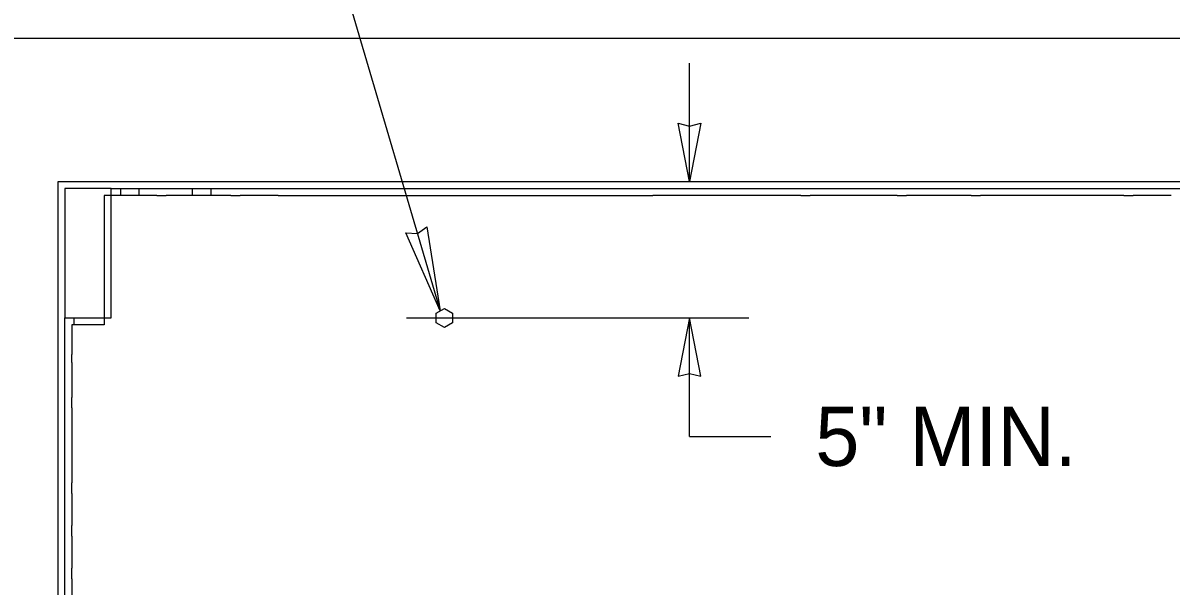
# Model space of a CAD drawing. Extents: x 99862 to 103151, y 100000 to 105076.
# Drawn here: x 100100.8 to 100411, y 100539.9 to 100692.1 of the extents above; entities that cross this region are included whole.
import ezdxf

# ---------------------------------------------------------------- set-up
doc = ezdxf.new("R2010")
doc.units = 0
for name, color, linetype in [('Level 15', 7, 'Continuous'), ('Level 20', 7, 'Continuous'), ('Level 3', 7, 'Continuous'), ('Level 4', 7, 'Continuous'), ('Level 5', 7, 'Continuous'), ('Level 50', 7, 'Continuous')]:
    doc.layers.add(name, color=color, linetype=linetype)

msp = doc.modelspace()

# ---------------------------------------------------------------- linework, layer by layer
at = {"layer": 'Level 15'}
for p, q in [((100182.1, 100720.99), (100213.58, 100614.29)), ((100280.92, 100649.23), (100280.92, 100681.23)), ((100204.47, 100612.36), (100296.92, 100612.36)), ((100280.92, 100580.36), (100280.92, 100612.36)), ((100280.92, 100580.36), (100302.92, 100580.36))]:
    msp.add_line(p, q, dxfattribs=at)
for points in [[(100280.92, 100649.23), (100277.83, 100664.96), (100280.92, 100664.23), (100284, 100664.96)], [(100213.58, 100614.29), (100204.26, 100635.34), (100207.42, 100635.17), (100209.98, 100637.03)], [(100280.92, 100612.36), (100277.83, 100596.63), (100280.92, 100597.36), (100284, 100596.63)]]:
    msp.add_lwpolyline(points, close=True, dxfattribs=at)
at = {"layer": 'Level 3'}
for p, q in [((100074.69, 100687.98), (100514.69, 100687.98)), ((100110.32, 100649.23), (100479.07, 100649.23)), ((100110.32, 100406.73), (100110.32, 100649.23)), ((100114.69, 100610.48), (100114.69, 100612.36))]:
    msp.add_line(p, q, dxfattribs=at)
at = {"layer": 'Level 4'}
for p, q in [((100124.69, 100647.36), (100464.69, 100647.36)), ((100112.19, 100408.61), (100112.19, 100612.36))]:
    msp.add_line(p, q, dxfattribs=at)
at = {"layer": 'Level 5'}
for p, q in [((100124.69, 100647.36), (100112.19, 100647.36)), ((100112.19, 100647.36), (100112.19, 100612.36)), ((100124.69, 100612.36), (100124.69, 100647.36)), ((100127.19, 100647.36), (100127.19, 100645.48)), ((100132.19, 100647.36), (100132.19, 100645.48)), ((100146.57, 100647.36), (100146.57, 100645.48)), ((100151.57, 100647.36), (100151.57, 100645.48)), ((100122.82, 100645.48), (100122.82, 100643.59)), ((100129.78, 100645.48), (100122.82, 100645.48)), ((100132.28, 100645.48), (100129.78, 100645.48)), ((100137.04, 100645.48), (100132.28, 100645.48)), ((100137.04, 100645.48), (100139.54, 100645.48)), ((100149.78, 100645.48), (100139.54, 100645.48)), ((100152.28, 100645.48), (100149.78, 100645.48)), ((100157.04, 100645.48), (100152.28, 100645.48)), ((100157.04, 100645.48), (100159.54, 100645.48)), ((100169.78, 100645.48), (100159.54, 100645.48)), ((100169.78, 100645.48), (100271.03, 100645.48)), ((100273.53, 100645.48), (100271.03, 100645.48)), ((100277.04, 100645.48), (100273.53, 100645.48)), ((100279.54, 100645.48), (100277.04, 100645.48)), ((100291.03, 100645.48), (100279.54, 100645.48)), ((100293.53, 100645.48), (100291.03, 100645.48)), ((100297.04, 100645.48), (100293.53, 100645.48)), ((100299.54, 100645.48), (100297.04, 100645.48)), ((100311.03, 100645.48), (100299.54, 100645.48)), ((100311.03, 100645.48), (100313.53, 100645.48)), ((100317.04, 100645.48), (100313.53, 100645.48)), ((100319.54, 100645.48), (100317.04, 100645.48)), ((100331.03, 100645.48), (100319.54, 100645.48)), ((100333.53, 100645.48), (100331.03, 100645.48)), ((100337.04, 100645.48), (100333.53, 100645.48)), ((100337.04, 100645.48), (100339.54, 100645.48)), ((100351.03, 100645.48), (100339.54, 100645.48)), ((100353.53, 100645.48), (100351.03, 100645.48)), ((100357.04, 100645.48), (100353.53, 100645.48)), ((100357.04, 100645.48), (100359.54, 100645.48)), ((100371.03, 100645.48), (100359.54, 100645.48)), ((100373.53, 100645.48), (100371.03, 100645.48)), ((100378.29, 100645.48), (100373.53, 100645.48)), ((100380.79, 100645.48), (100378.29, 100645.48)), ((100391.03, 100645.48), (100380.79, 100645.48)), ((100393.53, 100645.48), (100391.03, 100645.48)), ((100398.29, 100645.48), (100393.53, 100645.48)), ((100398.29, 100645.48), (100400.79, 100645.48)), ((100411.03, 100645.48), (100400.79, 100645.48)), ((100122.82, 100643.59), (100122.82, 100620.5)), ((100122.82, 100620.5), (100122.82, 100616.93)), ((100122.82, 100616.93), (100122.82, 100610.48)), ((100112.19, 100612.36), (100124.69, 100612.36)), ((100114.07, 100610.48), (100114.07, 100602.45)), ((100117.66, 100610.48), (100114.07, 100610.48)), ((100120.16, 100610.48), (100117.66, 100610.48)), ((100122.82, 100610.48), (100120.16, 100610.48)), ((100114.07, 100600.33), (100114.07, 100602.45)), ((100114.07, 100600.33), (100114.07, 100590.91)), ((100114.07, 100588.06), (100114.07, 100590.91)), ((100114.07, 100588.06), (100114.07, 100579.36)), ((100114.07, 100579.36), (100114.07, 100576.51)), ((100114.07, 100576.51), (100114.07, 100567.81)), ((100114.07, 100564.97), (100114.07, 100567.81)), ((100114.07, 100564.97), (100114.07, 100556.27)), ((100114.07, 100553.42), (100114.07, 100556.27)), ((100114.07, 100553.42), (100114.07, 100544.72)), ((100114.07, 100541.87), (100114.07, 100544.72)), ((100114.07, 100541.87), (100114.07, 100533.17))]:
    msp.add_line(p, q, dxfattribs=at)
at = {"layer": 'Level 50'}
for p, q in [((100212.47, 100613.64), (100214.69, 100614.93)), ((100212.47, 100611.07), (100212.47, 100613.64)), ((100214.69, 100614.93), (100216.92, 100613.64)), ((100216.92, 100613.64), (100216.92, 100611.07)), ((100214.69, 100609.79), (100212.47, 100611.07)), ((100216.92, 100611.07), (100214.69, 100609.79))]:
    msp.add_line(p, q, dxfattribs=at)

# ---------------------------------------------------------------- texts
at = {"layer": 'Level 20'}
msp.add_text('5" MIN.', height=16, rotation=360, dxfattribs=at).set_placement((100314.92, 100572.36))

doc.saveas('drawing.dxf')
